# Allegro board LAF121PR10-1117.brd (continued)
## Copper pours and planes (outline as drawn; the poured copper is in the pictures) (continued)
LG1_APU on IN3 (solid shape): 154.46,83.92 154.46,82.58 154.46,82.58 154.46,81.69 154.34,81.57 153.59,81.57 153.45,81.71 153.45,82.48 153.5,82.54 153.52,82.54 153.79,82.77 153.72,83.12 153.69,83.16 153.83,83.31 153.83,83.89 153.92,83.98 154.4,83.98
LG1_APU on IN3 (solid shape): 156.91,74.47 156.91,73.61 156.98,73.54 156.98,73.54 157.05,73.44 157.14,73.37 157.15,73.37 157.26,73.26 157.74,73.26 157.88,73.12 157.87,73.09 157.87,73 157.89,72.91 157.89,72.9 157.89,72.5 157.89,72.49 157.87,72.37 157.89,72.25 157.89,72.24 157.89,71.84 157.89,71.83 157.87,71.71 157.89,71.59 157.89,71.58 157.89,71.48 157.85,71.4 157.76,71.39 157.35,71.25 157.37,70.82 157.4,70.75 157.28,70.46 157.4,70.16 157.37,70.09 157.35,69.66 157.76,69.52 157.85,69.51 157.89,69.43 157.89,68.47 157.55,68.13 156.65,68.13 156.35,68.43 156.35,72.27 155.94,72.67 155.93,72.67 155.5,73.11 155.5,74.54 155.57,74.61 156.77,74.61
LG1_CHG on BOTTOM (solid shape): 194.67,48.06 194.67,47.73 194.51,47.57 193.21,47.57 193.12,47.66 193.12,48.06 193.3,48.24 194.5,48.24
LG1_VGA on TOP (solid shape): 85.49,128.72 85.49,127.83 85.35,127.69 84.29,127.69 84.29,127.69 84.24,127.74 84.24,128.51 84.24,128.53 84.24,128.8 84.27,128.83 85.37,128.83
LG1_VGA on BOTTOM (solid shape): 90.08,128.47 90.08,127.8 89.96,127.68 89.94,127.68 89.84,127.58 88.92,127.58 88.6,127.9 88.6,128.37 88.91,128.67 89.87,128.67
LG1_VGA on IN3 (solid shape): 89.91,128.54 89.91,127.73 89.75,127.57 89.56,127.57 89.47,127.58 89.37,127.57 84.78,127.57 84.77,127.57 84.64,127.59 84.52,127.57 84.51,127.57 83.59,127.57 83.42,127.73 83.42,128.61 83.57,128.76 89.7,128.76
LG2_APU on TOP (solid shape): 155.28,85.33 155.27,85.32 155.27,84.32 155.33,84.27 155.33,83.75 155.45,83.63 155.45,83.33 155.48,83.3 155.48,82.72 155.42,82.66 155.12,82.66 155.02,82.76 155.02,84 155.02,84 155.02,84.15 155.05,84.18 155.05,85.34 155.12,85.4 155.21,85.4
LG2_APU on TOP (solid shape): 161.15,65.3 161.15,64.51 160.89,64.25 159.95,64.25 159.79,64.42 159.79,64.65 159.8,64.75 159.79,64.85 159.79,65.26 159.8,65.32 159.94,65.46 160.98,65.46
LG2_APU on BOTTOM (solid shape): 161.17,69.43 161.17,68.71 160.95,68.49 160.32,68.49 160.32,68.49 159.93,68.89 159.93,69.78 160.03,69.88 160.72,69.88
LG2_APU on IN3 (solid shape): 155.48,83.56 155.48,82.91 155.84,82.55 155.84,81.88 155.68,81.73 154.89,81.73 154.83,81.79 154.83,82.65 154.83,82.66 154.83,83.61 154.94,83.72 155.31,83.72
LG2_APU on IN3 (solid shape): 161.55,70.15 161.55,64.66 161,64.1 160.26,64.1 160.11,64.18 159.93,64.17 159.91,64.16 159.82,64.24 159.79,64.3 159.79,64.66 159.8,64.75 159.79,64.85 159.79,65.27 159.8,65.36 159.79,65.46 159.79,65.63 160.02,65.87 160.02,66.18 160.04,66.21 160.07,66.23 160.38,66.44 160.32,66.82 160.29,66.89 160.32,66.95 160.41,67.2 160.3,67.45 160.27,67.52 160.3,67.59 160.39,67.98 160.07,68.21 160.04,68.22 160.02,68.26 160.02,70.37 160.24,70.59 161.11,70.59
LG2_CHG on BOTTOM (solid shape): 199.04,42.71 199.04,41.76 198.67,41.38 198.46,41.38 198.15,41.69 198.15,41.87 198.22,41.93 198.22,42.59 198.47,42.84 198.92,42.84
LG2_VGA on TOP (solid shape): 77.68,130.22 78.02,130.22 78.04,130.24 78.14,130.14 78.14,129.89 78.02,129.77 77.74,129.77 77.42,130.09 77.39,130.09 77.29,130.2 76.34,130.2 76.28,130.26 76.28,130.35 76.34,130.4 77.49,130.4
LG2_VGA on TOP (solid shape): 89.32,132.27 89.48,132.23 89.64,132.27 89.9,132.27 89.96,132.2 89.96,131.36 89.84,131.24 88.86,131.24 88.72,131.38 88.72,132.08 88.91,132.27
LG2_VGA on BOTTOM (solid shape): 85.58,132.02 85.58,131.42 85.45,131.29 84.39,131.29 84.31,131.36 84.31,132.23 84.41,132.33 85.28,132.33
LG2_VGA on IN3 (solid shape): 79.31,130.05 79.31,129.97 79.08,129.75 78.76,129.75 78.76,129.74 77.7,129.74 77.56,129.88 77.56,130.13 77.66,130.22 78.15,130.22 78.15,130.22 78.55,130.22 78.79,130.45 78.9,130.45
LG2_VGA on IN3 (solid shape): 89.18,132.39 89.48,132.23 89.78,132.39 89.91,132.39 90.1,132.2 90.1,131.39 89.9,131.19 83.5,131.19 83.35,131.34 83.35,132.24 83.5,132.39
LG_1.2V on TOP (solid shape): 38.67,26.73 38.67,26.35 38.52,26.2 38.36,26.2 37.78,26.78 37.63,26.78 37.55,26.86 37.55,27.62 37.6,27.67 37.73,27.67
LG_NB on TOP (solid shape): 158.5,87.23 158.63,87.21 158.76,87.23 158.77,87.23 158.85,87.23 158.9,87.18 158.9,86.79 158.81,86.71 157.68,86.71 157.57,86.6 156.63,86.6 156.56,86.68 156.56,86.8 156.62,86.87 157.6,86.87 157.6,86.9 157.93,87.23 158.49,87.23
LG_NB on BOTTOM (solid shape): 163.19,102.67 163.19,101.59 163.06,101.46 162.22,101.46 161.99,101.68 161.99,102.64 162.12,102.76 163.11,102.76
LG_NB on IN2 (solid shape): 164.15,102.62 164.15,101.52 164.03,101.4 162.36,101.4 161.97,101.8 161.97,102.71 162.09,102.83 163.94,102.83
LG_NB on IN2 (solid shape): 159.42,87.64 159.42,86.89 159.22,86.7 158.8,86.7 158.8,86.7 158.58,86.7 158.54,86.7 158.01,86.7 157.97,86.7 157.85,86.7 157.74,86.81 157.74,87.22 158.1,87.58 158.21,87.61 158.28,87.52 158.7,87.21 158.98,87.65 158.99,87.74 159.07,87.78 159.28,87.78
LX1_APU on TOP (solid shape): 156.19,72.14 156.19,68.94 156.36,68.78 156.36,66.98 156.56,66.77 157.54,66.77 157.64,66.76 157.74,66.77 158.12,66.77 158.2,66.7 158.2,65.83 158.06,65.69 156.85,65.69 155.93,64.77 155.93,60.22 155.77,60.07 154.3,60.07 153.7,60.66 153.7,64.24 153.45,64.5 152.89,65.07 152.89,68.06 153.45,68.63 153.45,72.09 153.74,72.38 155.96,72.38
LX1_APU on TOP (solid shape): 153.69,85.3 153.69,83.35 153.56,83.23 153.54,83.23 153.2,83.14 153.1,82.8 153.11,82.77 153.08,82.75 153.08,82.12 152.99,82.03 152.43,82.03 152.33,82.13 152.33,82.79 152.6,83.06 152.6,83.28 153.45,84.12 153.45,85.28 153.53,85.37 153.62,85.37
LX1_APU on BOTTOM (solid shape): 156.21,72.3 156.21,68.16 156.43,67.95 156.43,67 156.68,66.76 157.49,66.76 157.59,66.74 157.69,66.76 158.22,66.76 158.46,66.51 158.46,63.41 158.24,63.19 156.89,63.19 156.89,64.12 156.13,64.12 156.13,63.19 153.3,63.19 152.94,63.56 152.94,67.9 153.49,68.46 153.49,72.21 153.73,72.45 156.07,72.45
LX1_APU on IN3 (solid shape): 155.18,69.79 155.18,68.54 155.18,67 155.07,66.89 155.04,66.9 154.91,66.91 154.79,66.88 154.78,66.87 154.51,66.87 154.5,66.88 154.35,66.91 154.2,66.88 154.19,66.87 153.69,66.87 153.63,66.94 153.63,68.59 153.69,68.65 153.69,69.77 153.94,70.02 154.95,70.02
LX1_APU on IN3 (solid shape): 153.7,83.99 153.7,83.71 153.69,83.65 153.7,83.5 153.44,83.24 153.42,83.24 153.12,83.02 153.19,82.65 153.21,82.58 153.18,82.51 152.94,82.27 152.15,82.27 152.1,82.33 152.1,82.58 152.11,82.59 152.11,82.68 153.15,83.72 153.15,83.93 153.29,84.08 153.61,84.08
LX1_CHG on TOP (solid shape): 190.61,54.44 190.61,53.75 190.46,53.6 188.02,53.6 187.82,53.81 187.82,54.52 188.07,54.77 190.28,54.77
LX1_CHG on BOTTOM (solid shape): 202.85,44.94 202.85,44.81 202.79,44.75 202.1,44.75 201.96,44.75 200.25,43.03 199.17,43.03 199.11,43.09 199.11,43.92 199.3,44.11 200.12,44.11 200.88,44.87 201.39,44.87 201.52,45 202.79,45
LX1_CHG on BOTTOM (solid shape): 190.64,54.2 190.73,53.85 191.08,53.76 193.52,51.32 197.9,51.32 198.03,51.19 198.03,48.65 197.9,48.52 191.93,48.52 189.44,51.01 185.94,51.01 185.83,51.11 185.83,54.62 186.15,54.94 189.9,54.94
LX1_VGA on TOP (solid shape): 77.34,128.75 77.47,128.75 77.72,128.5 78.09,128.5 78.09,128.51 78.38,128.51 78.52,128.65 79.03,128.65 79.09,128.58 79.09,128.07 78.96,127.95 78.2,127.95 78.07,128.08 77.82,128.08 77.77,128.09 77.72,128.09 77.66,128.16 77.66,128.3 77.4,128.56 77.34,128.56 77.3,128.6 76.34,128.6 76.28,128.66 76.28,128.75 76.34,128.8 77.29,128.8
LX1_VGA on TOP (solid shape): outline of 213 points within 85.02,123.93 97.73,128.17
LX1_VGA on BOTTOM (solid shape): 97.28,127.79 97.28,127.76 97.37,127.42 97.71,127.32 97.76,127.33 97.77,127.31 97.77,127.19 97.74,127.18 97.51,126.84 97.74,126.51 97.77,126.5 97.77,126.36 97.67,126.26 97.64,126.26 97.32,126.17 97.22,125.84 97.23,125.81 97.04,125.62 95.35,125.62 94.36,126.61 94.23,126.48 93.41,127.3 92.87,126.76 93.63,126 93.63,124.41 93.1,123.88 92.3,123.88 92.03,124.02 91.75,123.9 91.74,123.88 91.67,123.88 91.65,123.9 91.37,124.02 91.1,123.88 89.82,123.88 89.52,124.19 89.68,124.78 89.08,124.62 89.06,124.65 85.12,124.65 85.05,124.72 85.05,127.24 85.23,127.41 89.17,127.41 89.47,126.87 89.77,127.41 90.06,127.41 91.39,128.74 91.52,128.74 91.53,128.75 92.64,128.75 94.03,130.13 94.94,130.13
LX1_VGA on IN3 (solid shape): 89.73,125.86 89.73,125.14 89.57,124.98 88.65,124.98 88.49,125.14 88.49,125.72 88.65,125.88 89.15,125.88 89.31,126.04 89.55,126.04
LX2_APU on TOP (solid shape): 164.33,68.88 164.33,65.03 164.68,64.69 165.06,64.69 165.94,63.81 166.59,63.81 166.81,63.59 166.81,60.15 166.83,60.13 166.63,59.93 164.68,59.93 164.33,60.28 164.33,62.21 164.21,62.33 161.69,62.33 161.47,62.56 161.47,63.86 161.45,63.88 161.45,68.96 161.51,69.02 164.19,69.02
LX2_APU on TOP (solid shape): 155.69,85.35 155.69,84.21 156.26,83.64 156.22,83.6 156.15,83.2 156.49,82.99 156.56,82.96 156.6,82.89 156.6,82.41 156.54,82.35 156.01,82.35 155.62,82.74 155.62,83.64 155.46,83.79 155.46,84.31 155.47,84.31 155.47,85.36 155.5,85.39 155.65,85.39
LX2_APU on BOTTOM (solid shape): 164.31,68.88 164.31,64.95 164.89,64.37 165.65,64.37 166.04,63.98 166.78,63.98 166.98,63.79 166.98,61.18 166.71,60.92 164.81,60.92 164.81,61.83 164.05,61.83 164.05,60.92 161.93,60.92 161.53,61.32 161.53,69.03 164.16,69.03
LX2_APU on IN3 (solid shape): 163.65,69.81 163.65,63.58 163.57,63.5 162.67,63.5 162.6,63.57 162.6,64.71 162.42,64.88 162.42,69.78 162.58,69.94 163.52,69.94
LX2_APU on IN3 (solid shape): 156,83.96 156,83.78 156.2,83.58 156.18,83.55 156.22,83.09 156.68,83.05 156.71,83.08 157.16,82.62 157.16,82.28 157.1,82.22 156.25,82.22 156.15,82.32 155.96,82.5 155.96,82.6 155.6,82.96 155.6,83.61 155.55,83.66 155.55,84.05 155.62,84.12 155.84,84.12
LX2_CHG on TOP (solid shape): 193.02,45.7 193.02,43.52 192.92,43.42 191.91,43.42 191.7,43.62 191.7,45.65 191.83,45.78 192.95,45.78
LX2_CHG on BOTTOM (solid shape): 197.83,41.7 197.83,41.69 198.39,41.13 198.6,41.13 199.74,42.27 202.27,42.27 202.27,41.46 202.26,41.44 200.12,41.44 199.22,40.55 197.7,40.55 196.38,39.23 196.17,39.23 193.36,42.04 193.26,42.35 192.95,42.45 192.82,42.58 192.82,42.58 192.74,42.66 192.78,42.7 192.8,42.71 192.79,43.39 192.42,42.82 192.44,42.71 192.34,42.65 191.96,42.65 191.75,42.72 191.54,42.65 191.33,42.65 191.12,42.72 190.91,42.65 190.69,42.65 190.36,42.7 190.14,42.46 190.14,42.44 189.82,42.13 186.04,42.13 185.86,42.3 185.86,45.63 186,45.77 193.77,45.77
LX2_VGA on TOP (solid shape): 78.71,131.57 78.71,131.09 77.96,130.35 77.73,130.35 77.48,130.59 76.35,130.59 76.28,130.66 76.28,130.75 76.29,130.75 77.45,130.75 78.01,131.31 78.01,131.5 78.14,131.63 78.65,131.63
LX2_VGA on TOP (solid shape): 95.82,136.46 95.82,136.28 95.76,136.19 95.65,136.21 95.28,136.29 95.04,136 95.01,135.93 94.95,135.91 94.71,135.31 95.33,135.51 95.36,135.57 95.42,135.6 95.54,135.62 95.65,135.69 95.76,135.71 95.82,135.62 95.82,133.09 95.32,132.59 91.97,132.59 91.83,132.46 90.15,132.46 90.11,132.42 89.8,132.42 89.48,132.94 89.16,132.42 85.24,132.42 85.07,132.58 85.07,135.24 85.28,135.44 89.06,135.44 89.46,135.84 90.01,135.77 89.95,136.33 90.15,136.53 90.23,136.56 90.3,136.53 90.54,136.42 90.79,136.5 90.85,136.52 90.92,136.5 91.16,136.42 91.39,136.52 91.42,136.54 91.45,136.55 91.59,136.45 91.75,136.42 91.89,136.44 92.01,136.51 92.05,136.52 92.08,136.51 92.5,136.47 92.66,136.85 92.68,136.94 92.76,136.98 95.3,136.98
LX2_VGA on BOTTOM (solid shape): 94.59,135.74 94.59,135.46 93.99,134.87 93.78,134.87 93.05,134.14 93.59,133.6 94.18,134.2 94.43,134.2 95.41,133.22 93.76,131.57 90.85,131.57 89.9,132.52 89.83,132.52 89.48,132.94 89.13,132.52 85.16,132.52 85.09,132.6 85.09,135.31 85.28,135.5 88.67,135.5 88.68,135.52 89.05,135.52 89.43,135.9 90.01,135.77 89.89,136.36 90.11,136.58 90.19,136.61 90.27,136.57 90.51,136.42 90.79,136.5 90.85,136.52 90.92,136.5 91.16,136.42 91.39,136.52 91.42,136.54 91.45,136.55 91.7,136.42 91.96,136.5 92.02,136.52 92.08,136.5 92.5,136.47 92.66,136.86 92.68,136.95 92.76,136.99 93.34,136.99
LX2_VGA on IN3 (solid shape): 79.01,131 79.01,130.86 78.5,130.35 77.68,130.35 77.59,130.45 77.59,130.73 77.75,130.89 78.16,130.89 78.51,131.24 78.77,131.24
LX2_VGA on IN3 (solid shape): 89.66,135.68 89.76,135.67 89.86,135.68 89.86,135.68 90.15,135.68 90.31,135.53 90.3,135.5 90.3,135.38 90.33,135.27 90.34,135.26 90.34,134.68 90.09,134.44 89.33,134.44 89.07,134.7 89.07,135.55 89.21,135.68 89.65,135.68
LX_1.2V on TOP (solid shape): 49.69,30.16 49.69,28.63 49.54,28.48 46.97,28.48 46.95,28.51 46.9,28.71 46.74,28.85 46.74,29.85 46.88,29.99 48.19,29.99 48.48,30.28 49.56,30.28
LX_1.2V on TOP (solid shape): 39.02,27.82 39.48,27.82 39.63,27.97 39.93,27.97 40,27.96 40.09,27.95 40.22,27.82 40.22,26.83 40.9,26.14 40.9,25.94 40.72,25.76 40.47,25.76 38.54,27.69 38.16,27.69 37.96,27.9 37.96,28 38.06,28.1 38.74,28.1
LX_1.2V on BOTTOM (solid shape): 49.99,29.26 49.99,25.38 49.9,25.29 47.54,25.29 47.2,25.64 46.55,25.64 46.46,25.73 43.83,25.73 43.73,25.83 43.73,26.81 43.76,26.83 46.64,26.83 46.8,26.98 46.8,28.24 46.95,28.53 46.8,28.83 46.8,29.27 46.88,29.35 49.9,29.35
LX_1.8VALW on TOP (solid shape): 177.45,55.49 177.45,53.14 177.2,52.89 175.29,52.89 175.17,53.02 175.17,54.61 175.29,54.73 176.44,54.73 176.69,54.99 176.69,55.43 176.82,55.56 177.39,55.56
LX_1.8VALW on BOTTOM (solid shape): 177.58,56.87 177.58,56.02 177.48,55.49 178.02,55.47 178.04,55.46 178.63,55.46 178.98,55.11 178.98,52.74 178.71,52.47 175.8,52.47 175.69,52.57 175.69,54.97 175.77,55.05 176.18,54.97 176.39,55.32 176.58,55.51 176.58,55.85 176.68,55.96 176.68,56.88 176.8,57 177.46,57
LX_3V on BOTTOM (solid shape): 26.68,45.9 26.77,45.85 26.77,45.75 27.09,45.23 27.4,45.75 27.4,45.85 27.49,45.9 27.96,45.9 28.2,45.66 28.2,42.34 27.7,41.84 25.01,41.84 24.05,40.87 22.24,40.87 21,42.11 21,42.68 21.04,42.72 21.87,42.72 21.9,42.76 21.93,42.76 22.39,43.21 23.4,43.21 23.73,43.54 23.73,44.98 24.65,45.9
LX_5V on BOTTOM (solid shape): 23.02,99.92 23.02,99.02 23.19,98.84 23.29,98.51 23.62,98.42 23.78,98.25 24.37,98.25 24.45,98.18 24.54,98.18 24.66,98.15 24.77,98.18 24.89,98.18 25.02,98.04 25.02,97.98 24.54,97.49 23.09,97.49 22.91,97.31 22.41,97.75 22.48,97.09 17.5,97.09 17.37,97.21 17.37,99.95 17.55,100.14 22.8,100.14
LX_+1.35VGPU on BOTTOM (solid shape): 149.09,111.36 149.09,109.36 148.65,109.01 149.09,108.67 149.09,108.16 148.27,107.34 143.86,107.34 143.73,107.46 143.73,108.48 143.86,108.61 145.63,108.61 146.2,109.17 146.2,111.51 146.34,111.65 148.8,111.65
LX_+VDDP on TOP (solid shape): 162.35,47.42 162.35,45.96 162.2,45.8 159.65,45.8 159.46,46 159.46,47.68 159.53,47.75 162.02,47.75
LX_+VDDP on BOTTOM (solid shape): 162.35,47.29 162.35,45.34 162.61,45.08 164.3,45.08 164.4,44.98 164.4,43.63 164.2,43.44 162.94,43.44 162.42,43.65 162.33,43.1 162.33,42.25 162.18,42.11 159.64,42.11 159,42.74 159,42.95 159.08,43.18 159,43.4 159,43.59 159.08,43.81 159,44.03 159,44.22 159.08,44.45 159,44.67 159,44.86 159.08,45.08 159,45.3 159,45.49 159.08,45.72 159,45.94 159,46.13 159.08,46.35 159,46.57 159,46.76 159.08,46.96 159.03,47.17 159.01,47.2 159.27,47.47 162.16,47.47
LX_NB on TOP (solid shape): 159.79,86.39 159.79,86 159.61,85.81 159.23,85.81 158.96,86.08 158.64,86.08 158.58,86.09 158.52,86.08 158.03,86.08 157.97,86.09 157.82,86.08 157.7,86.21 156.59,86.21 156.53,86.27 156.53,86.39 156.6,86.46 157.71,86.46 157.82,86.57 158.79,86.57 158.8,86.58 158.87,86.58 158.98,86.69 159.5,86.69
LX_NB on TOP (solid shape): 158.73,99.61 158.73,98.55 158.33,98.14 158.33,96.76 158.29,96.72 155.24,96.72 155.1,96.86 155.1,98.09 155.24,98.23 156.94,98.23 157.16,98.45 157.16,99.06 157.98,99.06 157.99,99 158,98.95 158.02,98.9 158.04,98.85 158.08,98.81 158.12,98.78 158.16,98.75 158.21,98.72 158.26,98.71 158.31,98.7 158.37,98.7 158.42,98.71 158.47,98.72 158.52,98.75 158.56,98.78 158.6,98.81 158.63,98.85 158.66,98.9 158.68,98.95 158.69,99 158.7,99.06 158.69,99.11 158.68,99.16 158.66,99.21 158.63,99.26 158.6,99.3 158.56,99.33 158.52,99.36 158.47,99.39 158.42,99.4 158.37,99.41 158.31,99.41 158.26,99.4 158.21,99.39 158.16,99.36 158.12,99.33 158.08,99.3 158.04,99.26 158.02,99.21 158,99.16 157.99,99.11 157.98,99.06 157.16,99.06 157.16,99.59 157.27,99.7 158.64,99.7
LX_NB on BOTTOM (solid shape): 159.82,86.59 159.87,86.56 159.93,86.54 159.93,85.98 159.86,85.92 159.16,85.92 158.98,86.1 157.76,86.1 157.69,86.17 157.69,86.51 157.77,86.59
LX_NB on BOTTOM (solid shape): 156.55,101.09 156.58,101.08 156.63,101.07 156.68,101.07 156.72,101.08 156.75,101.09 162.59,101.09 162.78,100.9 162.78,98.61 162.47,98.29 158.53,98.29 158.01,97.77 158.01,95.93 157.83,95.75 155.04,95.75 154.91,95.88 154.91,97.21 154.97,97.28 155.74,97.28 155.8,97.34 155.8,98.1 155.74,98.17 154.97,98.17 154.91,98.23 154.91,99.06 157.98,99.06 157.99,99 158,98.95 158.02,98.9 158.04,98.85 158.08,98.81 158.12,98.78 158.16,98.75 158.21,98.72 158.26,98.71 158.31,98.7 158.37,98.7 158.42,98.71 158.47,98.72 158.52,98.75 158.56,98.78 158.6,98.81 158.63,98.85 158.66,98.9 158.68,98.95 158.69,99 158.7,99.06 158.69,99.11 158.68,99.16 158.66,99.21 158.63,99.26 158.6,99.3 158.56,99.33 158.52,99.36 158.47,99.39 158.42,99.4 158.37,99.41 158.31,99.41 158.26,99.4 158.21,99.39 158.16,99.36 158.12,99.33 158.08,99.3 158.04,99.26 158.02,99.21 158,99.16 157.99,99.11 157.98,99.06 154.91,99.06 154.91,100.71 155.29,101.09
REGOUT on TOP (solid shape): 20.46,86.29 20.61,86.25 20.76,86.29 20.77,86.29 21.09,86.29 21.11,86.26 21.11,85.55 21.28,85.38 22.1,85.38 22.17,85.31 22.17,84.65 22.08,84.55 21.71,84.56 21.07,84.56 21.05,84.55 20.65,84.55 20.56,84.64 20.57,84.66 20.48,84.91 20.22,84.98 20.14,85 20.1,85.08 20.1,86.21 20.18,86.29 20.45,86.29
REGOUT on BOTTOM (solid shape): 21.18,86 21.18,85.53 21.37,85.34 21.81,85.34 22.01,85.15 22.01,84.32 21.88,84.2 20.1,84.2 19.97,84.32 19.97,85.97 20.14,86.14 21.04,86.14
RING2 on TOP (solid shape): 19.27,15.3 19.27,13.58 19.02,13.33 18.13,13.33 18,13.46 18,15.3 18.2,15.49 19.08,15.49
RING2 on TOP (solid shape): 28.51,18.23 28.51,17.38 27.99,16.86 27.99,15.95 27.92,15.88 27.82,15.88 27.77,15.93 27.77,16.96 28.08,17.27 28.08,18.22 28.19,18.33 28.41,18.33
RING2 on BOTTOM (solid shape): 28.99,18.22 28.99,16.57 28.29,15.87 20.99,15.87 20.71,15.59 20.69,15.59 20.42,15.49 20.32,15.22 20.32,15.2 20.04,14.92 18.07,14.92 18,14.98 18,15.36 18.13,15.49 19.47,15.49 20.66,16.68 27.74,16.68 28.05,16.99 28.05,17.09 28.08,17.11 28.08,18.23 28.19,18.35 28.86,18.35
RING2_R on TOP (solid shape): 17.75,13.71 17.75,13.32 18.06,13.01 18.77,13.01 18.94,12.84 18.94,11.86 18.77,11.68 18.77,9.27 18.51,9.01 17.28,9.01 17.09,9.2 17.09,11.47 17.75,12.12 17.75,12.6 17.62,12.73 17.55,12.83 17.44,12.91 17.15,13.2 17.15,13.81 17.18,13.84 17.62,13.84
RING2_R on BOTTOM (solid shape): 18.96,14.54 18.96,12.57 18.83,12.44 18,12.44 17.81,12.63 17.81,14.47 18,14.66 18.83,14.66
RING2_R on IN1 (solid shape): 17.91,10.19 17.91,9.17 17.85,9.11 16.51,9.11 16.32,9.3 16.32,10 16.64,10.31 17.78,10.31
RING2_R on IN1 (solid shape): 6.7,8 6.7,7.55 6.32,7.17 6,7.17 5.81,7.36 4.16,7.36 3.97,7.55 3.97,8.19 4.16,8.38 6.32,8.38
SLEEVE on TOP (solid shape): 27.82,18.18 27.82,17.23 27.58,16.99 27.58,15.93 27.54,15.9 27.4,15.9 27.38,15.92 27.38,18.22 27.49,18.33 27.67,18.33
SLEEVE on TOP (solid shape): 16.99,16 16.99,15.17 16.8,14.98 16.16,14.98 15.91,14.73 15.91,13.87 15.9,13.86 15.9,13.38 15.78,13.27 15.4,13.27 15.27,13.39 15.27,15.3 16.16,16.19 16.8,16.19
SLEEVE on BOTTOM (solid shape): 27.85,18.16 27.85,17.08 27.66,16.89 20.54,16.89 19.4,15.74 17.31,15.74 16.99,15.43 16.99,15.17 16.8,14.98 16.35,14.98 16.16,15.17 16.16,15.93 16.73,16.51 18.77,16.51 19.19,16.93 19.2,16.93 19.34,17.02 19.42,17.15 19.42,17.16 20.1,17.84 26.58,17.84 27.09,18.35 27.66,18.35
SLEEVE_R on TOP (solid shape): 16.86,13.71 16.86,9.27 16.73,9.14 15.53,9.14 15.27,9.39 15.27,12.31 16.1,13.14 16.1,13.77 16.16,13.84 16.73,13.84
SLEEVE_R on BOTTOM (solid shape): 15.78,14.6 15.78,13.01 15.91,12.89 16.73,12.89 16.8,12.82 16.8,12.38 16.73,12.31 15.34,12.31 15.02,12.63 15.02,14.66 15.08,14.73 15.66,14.73
SLEEVE_R on IN1 (solid shape): 15.76,11.67 15.76,9.94 15.46,9.64 14.74,9.64 14.04,10.35 14.04,11.56 14.29,11.81 15.62,11.81
SLEEVE_R on IN1 (solid shape): 5.81,17.84 5.81,17.33 5.43,16.95 3.34,16.95 3.15,17.14 3.15,17.71 3.34,17.9 4.61,17.9 4.99,18.28 5.37,18.28
SNUB1_CHG on TOP (solid shape): 190.05,51.85 190.05,51.04 189.9,50.88 186.77,50.88 186.6,51.06 186.6,51.95 186.7,52.05 189.85,52.05
SNUB2_CHG on TOP (solid shape): 190.41,45.7 190.41,44.2 190.25,44.05 188.07,44.05 187.92,44.2 187.92,44.69 188.02,44.79 188.98,44.79 189.24,45.04 189.24,45.73 189.31,45.8 190.31,45.8
SNUB_+1.35VGPU on TOP (solid shape): 151.01,111.34 151.01,108.96 150.97,108.92 150.01,108.92 149.87,109.06 149.87,110.4 149.34,110.93 149.34,111.56 149.36,111.59 150.76,111.59
SNUB_+VDDP on TOP (solid shape): 161.37,45.09 161.37,43.92 161.1,43.66 161.1,42.51 161.01,42.42 159.32,42.42 159.14,42.6 159.14,42.8 159.46,43.12 159.46,44.99 159.6,45.14 161.32,45.14
SPK_L+_CONN on TOP (solid shape): 27.25,7.37 27.25,5.74 26.68,5.16 26.68,3.41 26.95,3.15 26.95,1.9 26.74,1.7 25.22,1.7 25.17,1.75 25.17,2.98 25.66,3.48 25.66,5.14 26.39,5.86 26.44,5.86 26.44,5.91 26.5,5.98 26.5,6.7 26.43,6.77 26.43,7.37 26.51,7.45 27.17,7.45
SPK_L+_CONN on BOTTOM (solid shape): 14.83,6.54 14.83,3.87 14.7,3.74 14.19,3.74 14.07,3.87 14.07,6.54 14.19,6.66 14.7,6.66
SPK_L+_CONN on IN3 (solid shape): 16.48,2.92 22.86,2.92 22.87,2.91 23.02,2.88 23.17,2.91 23.18,2.92 24.61,2.92 25.05,3.36 25.83,3.36 26.02,3.17 26.02,2.48 25.69,2.15 15.72,2.15 14.02,3.86 14.02,4.76 14.14,4.88 14.51,4.88
SPK_L-_CONN on TOP (solid shape): 28.25,7.41 28.25,7.16 28.29,7.11 28.29,5.98 29.03,5.24 29.03,3.84 29.49,3.39 29.49,1.89 29.29,1.7 27.87,1.7 27.75,1.82 27.75,3.31 28.01,3.58 28.01,5.24 27.52,5.74 27.52,7.36 27.61,7.45 28.2,7.45
SPK_L-_CONN on BOTTOM (solid shape): 13.81,6.48 13.81,3.8 13.72,3.71 13.05,3.71 13,3.77 13,6.48 13.11,6.59 13.7,6.59
SPK_L-_CONN on IN3 (solid shape): 13.81,4.76 13.81,3.68 15.46,2.03 28.48,2.03 28.74,2.28 28.74,2.92 28.99,3.17 29.28,3.17 29.53,2.92 29.53,1.81 28.99,1.27 14.89,1.27 13.12,3.04 13.12,4.76 13.24,4.88 13.69,4.88
SPK_R+_CONN on TOP (solid shape): 19.61,5.96 19.91,5.8 20.21,5.96 20.56,5.96 20.81,5.8 21.09,5.88 21.16,5.9 21.23,5.87 21.29,5.81 21.36,5.77 21.37,5.77 21.56,5.58 23.28,5.58 23.34,5.52 23.34,4.82 23.28,4.76 21.08,4.76 20.85,4.97 20.54,5.05 20.04,5.05 19.74,4.98 19.51,4.77 19.15,4.77 19.1,4.77 19.04,4.76 17.12,4.76 16.86,5.01 16.86,5.84 16.99,5.96
SPK_R+_CONN on BOTTOM (solid shape): 17.37,6.03 17.37,5.01 17.18,4.82 16.54,4.82 16.1,5.27 16.1,6.54 16.23,6.66 16.73,6.66
SPK_R-_CONN on TOP (solid shape): 23.34,4.44 23.34,3.61 23.28,3.55 23.18,3.55 23.17,3.56 23.02,3.59 22.87,3.56 22.86,3.55 21.81,3.55 21.24,2.98 17.12,2.98 16.86,3.23 16.86,4 17.05,4.19 18.88,4.19 19,4.09 19.15,4.06 19.51,4.06 19.74,3.86 20.04,3.78 20.54,3.78 20.99,3.96 21.21,4.47 21.28,4.5 23.28,4.5
SPK_R-_CONN on BOTTOM (solid shape): 15.72,6.54 15.72,5.01 16.48,4.25 17.18,4.25 17.31,4.12 17.31,3.11 17.24,3.04 16.61,3.04 15.08,4.57 15.08,6.47 15.27,6.66 15.59,6.66
UG1_APU on TOP (solid shape): 151.82,73.78 151.82,71.85 151.67,71.69 151.07,71.69 150.9,71.87 150.9,72.52 151,72.62 151,73.76 151.11,73.87 151.73,73.87
UG1_APU on TOP (solid shape): 153.28,85.34 153.28,84.18 153.18,84.09 153.17,84.06 153.17,84.04 152.44,83.3 152.19,83.3 152.19,83.35 152,83.35 152,83.68 152.51,84.18 152.86,84.18 153.06,84.37 153.06,85.3 153.15,85.39 153.23,85.39
UG1_APU on BOTTOM (solid shape): 152.07,68.01 152.41,68.01 152.52,67.91 152.52,67.08 152.37,66.93 152,66.93 151.99,66.92 151.84,66.92 150.9,67.87 150.9,68.5 151.05,68.65 151.43,68.65
UG1_APU on IN3 (solid shape): 152.98,84.11 152.98,83.77 151.88,82.67 151.88,82.24 151.83,82.18 150.95,82.18 150.88,82.25 150.88,82.73 152.39,84.24 152.85,84.24
UG1_APU on IN3 (solid shape): 153.01,74.65 153.01,66.92 152.82,66.73 151.89,66.73 151.43,67.19 151.43,72.18 151.02,72.59 151.02,74.62 151.36,74.96 152.69,74.96
UG1_CHG on BOTTOM (solid shape): 194.66,54.4 194.66,53.45 194.47,53.25 193.77,53.25 193.58,53.45 193.58,54.4 193.71,54.52 194.53,54.52
UG1_VGA on TOP (solid shape): 85.52,122.78 85.52,122.22 85.36,122.06 85.05,122.06 84.72,122.4 84.01,122.4 83.88,122.42 83.75,122.4 83.74,122.4 83.63,122.51 83.63,123.12 83.8,123.3 85,123.3
UG1_VGA on TOP (solid shape): 77.53,128.24 77.53,128.2 77.53,128.1 77.67,127.97 77.72,127.96 77.75,127.96 77.78,127.96 77.95,127.79 77.95,127.62 77.76,127.43 77.64,127.43 77.6,127.46 77.56,127.49 77.29,127.77 77.3,127.84 77.29,127.91 77.29,128.04 77.19,128.14 76.36,128.14 76.3,128.2 76.3,128.37 76.33,128.41 77.36,128.41
UG1_VGA on BOTTOM (solid shape): 90.61,123.22 90.61,122.47 90.49,122.35 90.31,122.35 89.98,122.59 89.64,122.35 89.41,122.35 89.12,122.06 88.79,122.06 88.64,122.21 88.64,122.77 89.23,123.35 90.48,123.35
UG1_VGA on IN3 (solid shape): 90.53,123.43 90.53,122.74 90.41,122.61 89.49,122.61 89.33,122.78 89.33,123.67 89.54,123.88 90.08,123.88
UG1_VGA on IN3 (solid shape): 86.04,123.4 86.04,123.19 85.24,122.39 84.03,122.39 84.02,122.4 83.88,122.42 83.74,122.4 83.73,122.39 83.25,122.39 83,122.64 83,122.88 83.4,123.27 85.09,123.27 85.42,123.6 85.84,123.6
UG1_VGA on IN3 (solid shape): 77.68,127.94 77.85,127.94 77.91,127.94 78.55,127.3 78.24,126.99 77.98,126.99 77.72,127.25 77.62,127.45 77.42,127.55 77.42,127.72 77.66,127.96
UG2_APU on TOP (solid shape): 167.11,65.19 167.11,64.22 167,64.11 166.16,64.11 166.04,64.23 166.04,65.22 166.28,65.46 166.85,65.46
UG2_APU on TOP (solid shape): 156.08,85.36 156.08,84.42 156.17,84.33 156.21,84.28 156.26,84.23 156.32,84.18 156.76,84.18 157.18,83.77 157.18,83.56 157.18,83.56 157.18,83.39 157.05,83.26 156.93,83.26 156.86,83.28 156.83,83.35 156.7,83.62 156.41,83.7 156.39,83.69 156.07,84.01 156.07,84.04 155.85,84.26 155.85,85.33 155.91,85.39 156.05,85.39
UG2_APU on BOTTOM (solid shape): 166.96,70.29 166.96,69.88 166.96,69.87 166.96,68.82 166.65,68.51 166.31,68.51 166.1,68.72 166.1,70.24 166.35,70.49 166.76,70.49
UG2_APU on IN3 (solid shape): 167.2,71.32 167.2,64.41 166.9,64.1 165.87,64.1 165.71,64.27 165.71,70.62 165.8,70.85 165.71,71.08 165.71,71.23 165.77,71.32 165.79,71.43 165.8,71.45 165.83,71.49 167.03,71.49
UG2_APU on IN3 (solid shape): 158.3,83.49 158.3,82.69 158.19,82.58 157.77,82.58 157.76,82.59 157.47,82.59 156.81,83.24 156.82,83.27 156.72,83.6 156.4,83.69 156.37,83.69 156.24,83.82 156.24,84.1 156.35,84.21 157.58,84.21
UG2_CHG on BOTTOM (solid shape): 200.76,41.06 200.76,40.55 199.87,39.67 198.59,39.67 197.11,38.19 196.62,38.17 196.6,37.68 196.16,37.24 194.48,37.24 194.17,37.56 194.17,37.93 194.29,38.06 195.67,38.06 197.98,40.36 199.36,40.36 200.12,41.13 200.69,41.13
UG2_VGA on TOP (solid shape): 90.05,137.93 90.05,136.69 89.91,136.55 88.79,136.55 88.69,136.64 88.69,137.88 88.91,138.1 89.89,138.1
UG2_VGA on TOP (solid shape): 77.89,131.87 77.89,131.56 77.89,131.56 77.89,131.41 77.4,130.93 76.23,130.93 76.17,131 76.17,131.12 76.23,131.19 77.11,131.19 77.14,131.22 77.28,131.35 77.28,131.54 77.28,131.8 77.38,131.9 77.86,131.9
UG2_VGA on BOTTOM (solid shape): 85.56,137.71 85.56,136.86 85.43,136.74 84.25,136.74 84.04,136.94 84.04,137.74 84.2,137.89 85.38,137.89
UG2_VGA on IN3 (solid shape): 89.99,137.7 89.99,136.63 89.85,136.49 83.4,136.49 83.23,136.66 83.23,137.59 83.52,137.88 87.98,137.88 88.01,137.91 89.78,137.91
UG_NB on TOP (solid shape): 157.74,85.96 158.77,85.96 158.85,85.88 158.85,85.59 158.72,85.47 157.86,85.47 157.55,85.78 157.54,85.8 156.58,85.8 156.52,85.86 156.52,85.98 156.6,86.05 157.64,86.05
UG_NB on BOTTOM (solid shape): 163.62,96.39 163.62,95.44 163.53,95.35 162.61,95.35 162.22,95.74 162.22,96.41 162.33,96.52 163.49,96.52
UG_NB on IN1 (solid shape): 164.14,96.17 164.15,96.16 164.2,96.08 164.27,96.01 164.46,95.82 164.46,95.12 164.43,95.08 163.31,95.08 162.9,95.5 162.9,96.19 163.2,96.5 163.81,96.5
UG_NB on IN1 (solid shape): 159.91,85.02 159.91,84.48 159.81,84.38 158.79,84.38 158.35,84.81 158.36,84.84 158.26,85.16 157.94,85.26 157.92,85.25 157.65,85.51 157.65,85.82 157.78,85.95 158.97,85.95
USBC_B2B_S1 on TOP (solid shape): 49.3,123.59 49.3,122.42 48.38,121.51 48.38,119.87 48.2,119.69 46.83,119.69 46.54,119.97 46.54,119.98 45.68,120.84 44.95,120.84 44.91,120.89 44.91,122.26 44.93,122.28 45.65,122.28 45.69,122.24 46.06,122.24 46.27,122.46 47.48,122.46 47.92,122.91 47.92,123.27 48.44,123.79 49.09,123.79
USBC_B2B_S2 on TOP (solid shape): 58.52,129.19 58.52,127.04 58.35,126.87 57.09,126.87 56.85,127.11 56.85,127.76 56.7,127.91 55.7,127.91 55.51,128.1 55.51,128.52 55.62,128.63 57.72,128.63 57.88,128.79 57.88,129.1 58.02,129.25 58.46,129.25
N20141477 on TOP (solid shape): 156.24,102.17 156.24,101.09 156.82,100.52 156.82,99.63 156.69,99.5 155.23,99.5 155.1,99.63 155.1,102.04 155.29,102.23 156.18,102.23
N20141719 on TOP (solid shape): 158.63,61.93 158.63,61.35 158.96,61.02 159.83,61.02 159.88,60.97 159.88,60.31 159.83,60.26 157.64,60.26 157.59,60.31 157.59,61.98 157.64,62.03 158.53,62.03
N21022260 on BOTTOM (solid shape): 160.88,86.58 160.88,86.11 161.26,85.73 161.26,84.81 161.18,84.73 160.34,84.73 160.16,84.9 160.16,86.55 160.27,86.6 160.35,86.69 160.77,86.69
N21022300 on TOP (solid shape): 152.38,81.9 153.05,81.9 153.08,81.93 153.16,81.93 153.21,81.88 153.21,81.25 153.18,81.22 152.61,81.22 152.31,80.92 151.21,80.92 151.09,81.04 151.09,81.87 151.15,81.93 152.35,81.93
N21379353 on TOP (solid shape): 24.16,96.91 24.16,95.88 24.08,95.8 23.14,95.8 23.06,95.84 23.05,95.93 23.04,96.15 22.9,96.33 22.9,97.03 22.98,97.1 23.97,97.1
N21379353 on BOTTOM (solid shape): 23.42,97.07 23.42,97 23.56,96.86 24.37,96.86 24.5,96.74 24.5,96.57 24.49,96.56 24.46,96.43 24.48,96.3 24.49,96.27 24.43,96.21 24.43,96.13 24.34,96.05 23.29,96.05 22.8,96.54 22.81,96.56 22.79,96.7 22.72,96.81 22.7,96.83 22.7,96.9 22.89,97.09 23.4,97.09
N21741482 on TOP (solid shape): 46.83,135.49 46.83,135.47 46.86,135.47 46.95,135.38 48.28,135.38 48.42,135.24 48.42,133.68 48.22,133.47 43.89,133.47 43.81,133.55 43.81,134.04 44.62,134.86 44.62,136.05 44.89,136.32 46.01,136.32
N21741482 on TOP (solid shape): 52.37,139.77 52.5,139.73 52.63,139.77 52.64,139.77 54.45,139.77 54.63,139.59 54.63,138.1 54.53,137.99 53.26,137.99 52.76,137.5 52.76,135.2 53.02,134.95 53.02,134.26 53.48,133.8 54.21,133.8 54.26,133.75 54.26,133.22 54.19,133.14 52,133.14 50.8,134.35 50.8,136.85 50.2,137.45 50.2,139.09 50.33,139.21 51.11,139.21 51.28,139.38 51.36,139.38 51.75,139.77 52.35,139.77
N21741482 on BOTTOM (solid shape): 44.33,139.52 44.33,136.37 44.24,136.28 42.87,136.28 42.85,136.3 42.85,139.17 43.29,139.62 44.23,139.62
N21741482 on IN1 (solid shape): outline of 151 points within 42.85,133.42 52.56,140.14
N21741739 on TOP (solid shape): 54.72,137.65 54.72,134.93 54.66,134.87 53.62,134.87 53.06,135.43 53.06,137.21 53.67,137.82 54.56,137.82
N27633672 on TOP (solid shape): 29.07,120.03 29.07,118.38 28.16,117.47 26.66,117.47 26.48,117.65 26.48,118.08 26.13,118.42 26.13,118.99 26.26,119.12 26.27,119.12 26.48,119.06 26.68,119.12 27.15,119.12 27.4,119.38 28.1,119.38 28.23,119.5 28.23,120.01 28.29,120.07 29.03,120.07
N40598435 on BOTTOM (solid shape): 23.98,40.65 23.98,39.89 23.82,39.71 23.81,39.48 22.35,39.48 22.21,39.62 22.21,40.66 22.27,40.72 23.91,40.72
N40598500 on BOTTOM (solid shape): 24.23,102.07 24.23,101.28 24.16,101.21 22.59,101.21 22.37,101.43 22.37,102.03 22.51,102.17 24.13,102.17
N42785908 on BOTTOM (solid shape): 204.36,58.73 204.88,58.21 204.88,55.89 204.82,55.82 204.82,53.71 203.8,52.7 203.8,51.56 203.59,51.35 202.21,51.35 202.1,51.46 202.1,52.63 203.17,53.7 203.17,57.99 202.57,58.59 202.57,59.03 203.14,59.6 203.49,59.6
N42787460 on BOTTOM (solid shape): 200.05,46.49 200.05,44.57 200.03,44.56 199.13,44.56 199.09,44.6 199.09,46.57 199.14,46.62 199.92,46.62
N42787500 on BOTTOM (solid shape): 203.54,40.84 203.63,40.79 203.63,40.69 203.57,40.53 203.55,40.35 203.55,40.13 201.42,40.13 201.37,40.18 201.37,40.81 201.39,40.84
N48536391 on TOP (solid shape): 162.85,61.81 162.85,60.38 162.75,60.28 160.61,60.28 160.56,60.33 160.56,60.89 160.61,60.94 161.53,60.94 161.78,61.2 161.78,61.86 161.83,61.91 162.75,61.91
N48536437 on TOP (solid shape): 157.83,82.01 157.83,80.96 157.79,80.92 157.52,80.92 157.43,80.96 157.32,80.98 156.91,80.98 156.53,81.35 155.97,81.35 155.85,81.47 155.85,82.01 155.94,82.1 157.75,82.1
N48611923 on TOP (solid shape): 52.25,30.23 52.25,27.67 52.23,27.65 51.7,27.65 51.66,27.69 51.66,28.35 51.49,28.52 51.25,28.52 51.19,28.58 51.19,30.24 51.21,30.26 52.22,30.26
N48611968 on TOP (solid shape): 36.55,27.66 36.55,26.39 37.32,25.63 37.32,25 37.28,24.96 37.25,24.97 37.14,24.97 37.04,24.94 37.01,24.93 35.93,24.93 35.82,24.95 35.71,24.93 35.35,24.93 35.31,24.94 35.27,24.95 35.16,25.06 35.16,25.51 36.3,26.65 36.3,27.66 36.36,27.73 36.49,27.73
N48613121 on TOP (solid shape): 179.23,54.48 179.23,54.22 179.61,53.84 180.37,53.84 180.44,53.78 180.44,53.08 180.31,52.95 178.02,52.95 177.9,53.08 177.9,54.61 178.09,54.8 178.91,54.8
N48614395 on TOP (solid shape): 92.81,128.58 92.81,127.69 92.68,127.57 90.75,127.57 90.73,127.58 90.22,127.58 90.09,127.72 90.09,128.6 90.18,128.68 92.71,128.68
N48614410 on TOP (solid shape): 80.17,128.39 80.17,126.8 80.11,126.74 79.47,126.74 79.41,126.8 79.41,128.65 79.92,128.65
N48614492 on TOP (solid shape): 92.74,132.2 92.74,131.38 92.62,131.25 90.14,131.25 90.08,131.31 90.09,131.31 90.09,132.22 90.2,132.33 92.62,132.33
N48614505 on TOP (solid shape): 78.9,134.11 78.9,132.14 78.77,132.01 78.14,132.01 78.08,132.08 78.08,132.84 78.16,133.01 78.14,133.2 78.14,133.21 78.14,134.23 78.77,134.23
N48614539 on TOP (solid shape): 74.08,133.92 74.08,131.82 74.01,131.76 73.19,131.76 73.06,131.88 73.06,133.92 73.12,133.98 74.01,133.98
N48614551 on TOP (solid shape): 75.79,133.92 75.79,133.35 75.66,133.22 75.66,131.88 75.6,131.82 75.15,131.82 75.09,131.88 75.09,133.92 75.15,133.98 75.73,133.98
N48637416 on TOP (solid shape): 74.01,145.4 74.03,145.39 74.54,145.39 74.56,145.4 74.56,145.92 74.81,145.92 74.81,145.37 75.74,145.37 76.02,145.09 76.02,142.13 75.81,141.93 72.64,141.93 72.5,142.07 72.5,145.23 72.64,145.37 73.76,145.37 73.76,145.4 73.76,145.92 74.01,145.92
N48637416 on BOTTOM (solid shape): outline of 83 points within 72.57,141.09 77.95,146.55

Small or netless copper shapes (teardrops, artwork), in the pictures only: 226 on TOP, 18 on BOTTOM, 10 on IN1, 1 on IN2, 3 on IN3

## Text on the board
Ref Des/Silkscreen Bottom: H8 | H12 | M2X4L
User.Comments: LAF121P | Moopi | 2018-11-17 | 2017-11-17 | CAL51 | 1.0(A00)
Ref Des/Silkscreen Top: A
User.39: Width/space | trace Width | 5.5mil | 5.8mil | 5.3mil | 4.7mil | 4.4mil | 4.3mil | 7.4/5.4 | 5.1/3.5 | 4.7/3.9 | 4.4/4.3 | 5.3/4.2 | 5.3/5.9 | 4.4/6 | 4.7/5.3 | 3.5/6.4 | 3.5/4.6 | 7.2mil | 5.6mil | 4.2mil | 7 / 4.5 | 5.2 / 3.5 | L5/L7 | Ref | 100 ohm | 39 ohm | 45 ohm | 52 ohm | 72 ohm | 80 ohm
User.40: FIGURE | SIZE | 8.0 | 22.0 | 28.0 | 35.0 | 118.0 | 126.0 | 130.0 | 138.0 | 146.0 | 157.0 | 197.0 | 43.0 | 63.0 | 220.0 | 51.0x28.0 | 55.0x24.0 | 63.0x24.0 | 63.0x35.0 | 67.0x28.0 | 71.0x31.0 | 75.0x28.0 | 102.0x31.0 | 157.0x118.0 | 157.0x146.0 | 33.0x28.0 | DRILL CHART: TOP to BOTTOM | ALL UNITS ARE IN MILS | TOLERANCE | +3.0/-3.0 | +2.0/-2.0 | PLATED | NON-PLATED | QTY | 6327 | 19 | 18 | 8 | 5 | 2 | 1 | 4 | 7
User.43: stack-up setting ok
